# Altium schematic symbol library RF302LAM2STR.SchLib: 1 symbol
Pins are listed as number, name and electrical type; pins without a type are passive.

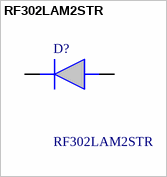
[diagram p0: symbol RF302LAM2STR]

## RF302LAM2STR
designator D?
Diode Standard 200 V 3A Surface Mount PMDTM; Manufacturer_Name: ROHM Semiconductor; Geometry.Height: 1.05mm
footprint RF302LAM2STR
pins: 1 K, 2 A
